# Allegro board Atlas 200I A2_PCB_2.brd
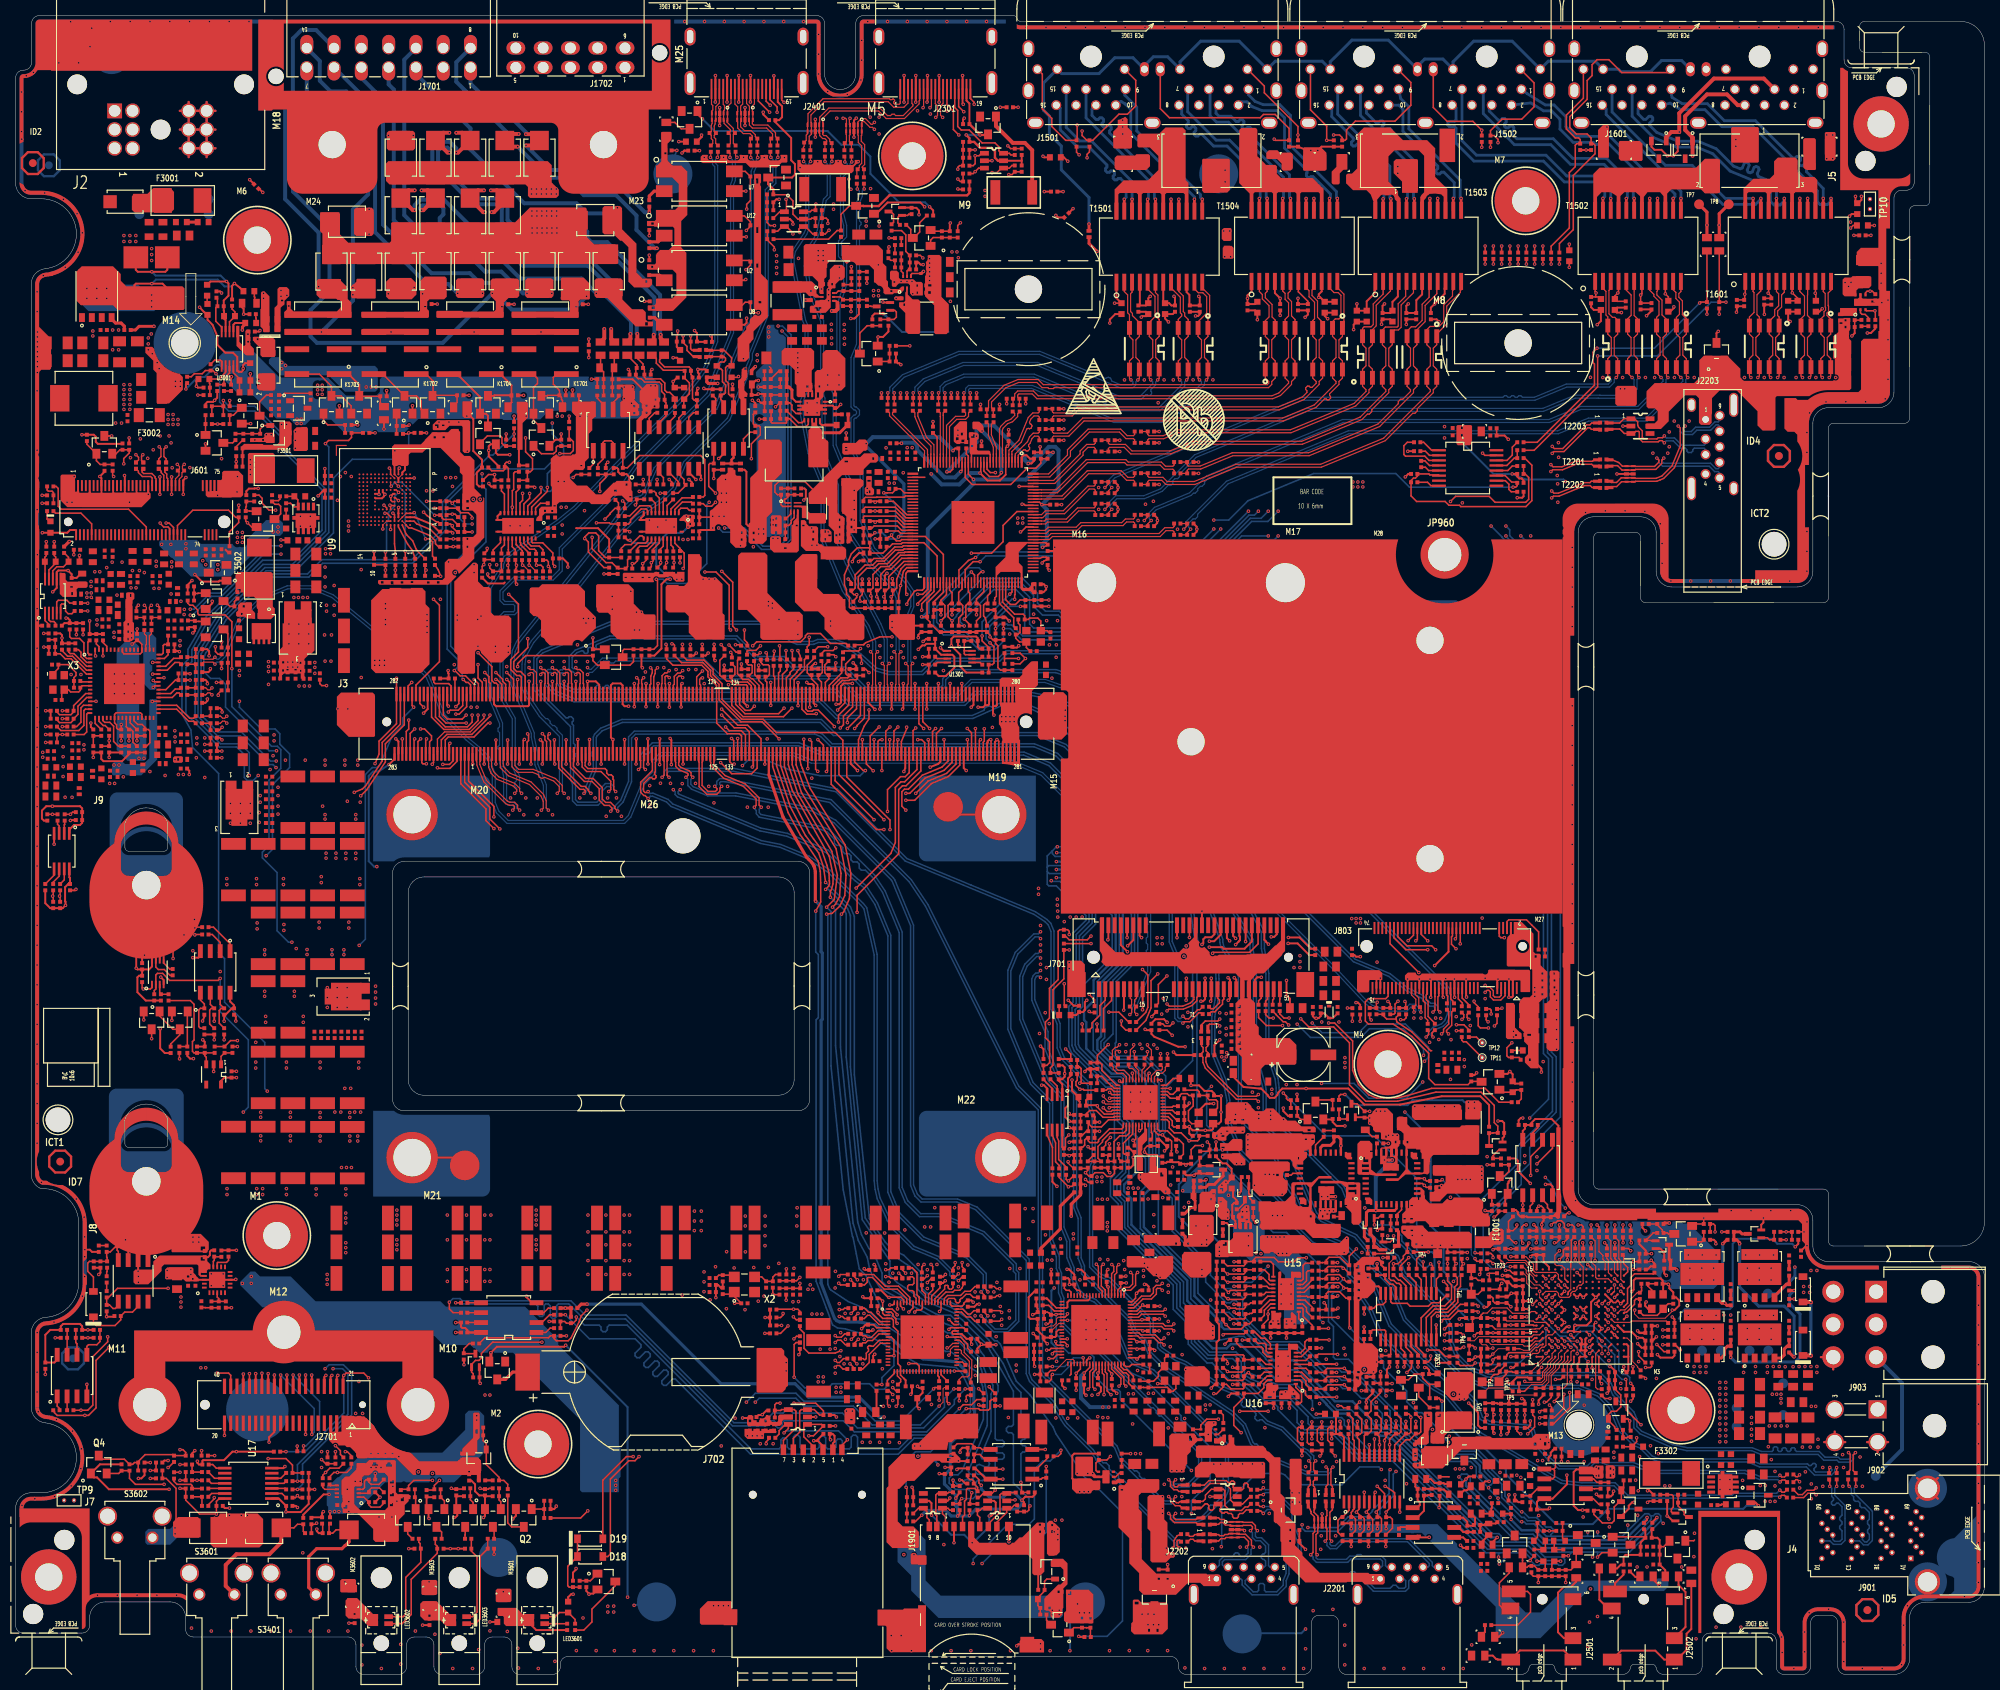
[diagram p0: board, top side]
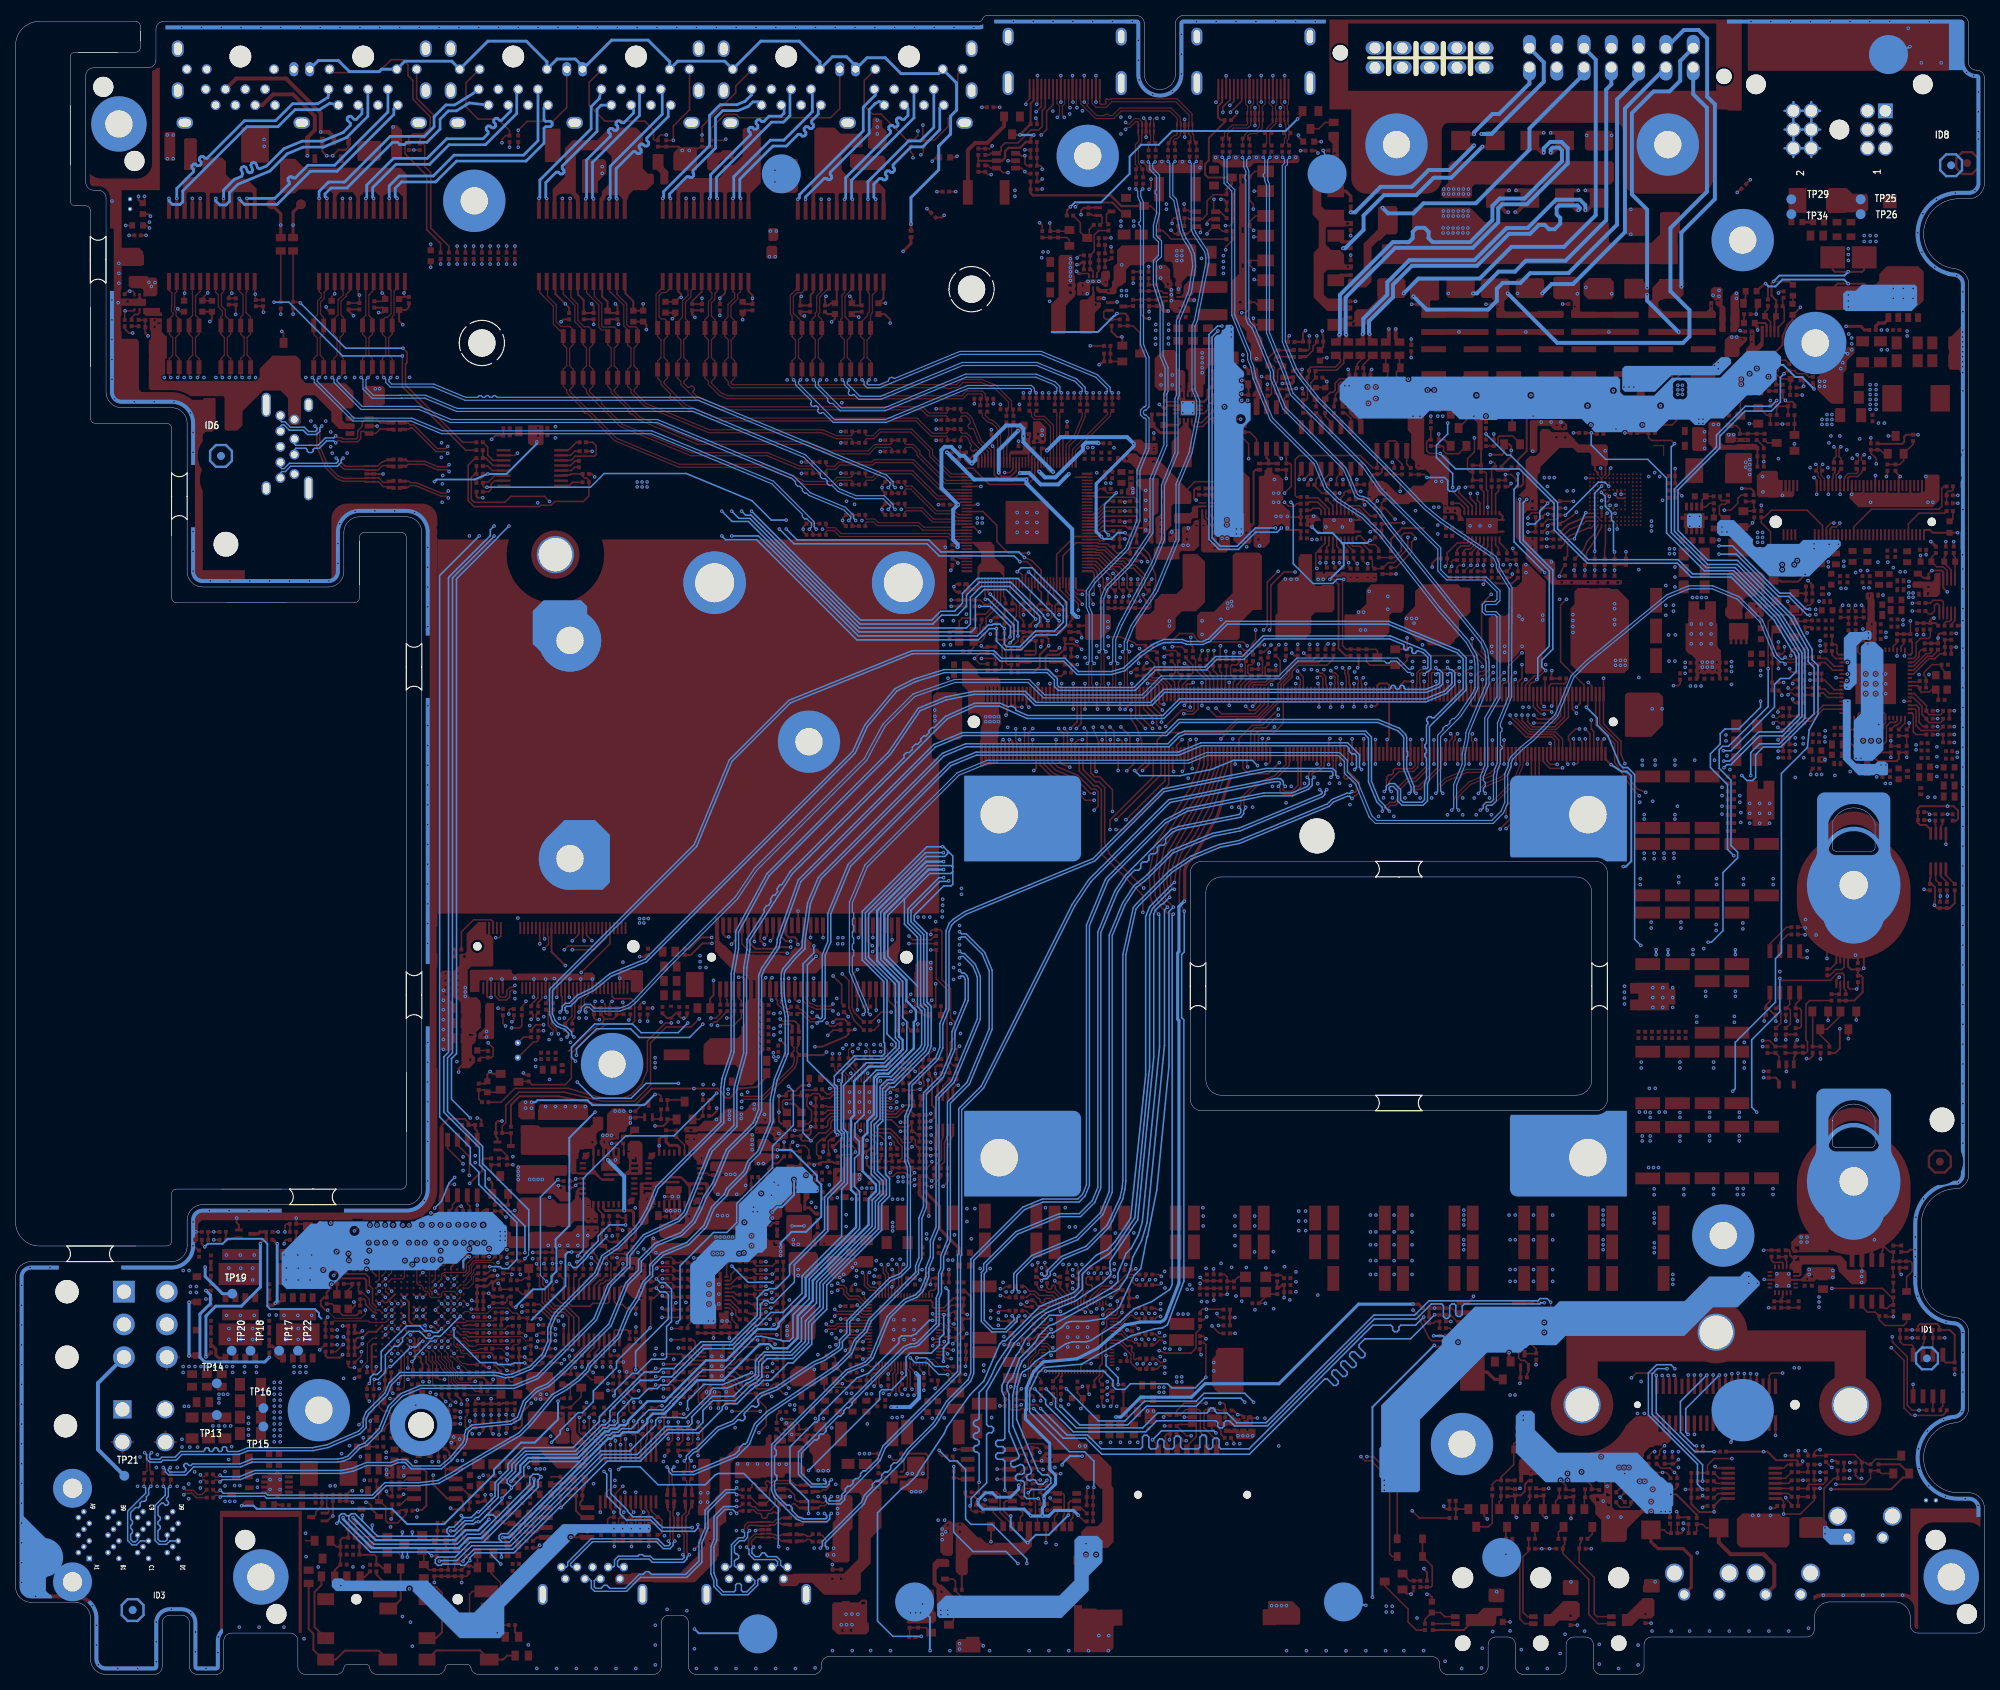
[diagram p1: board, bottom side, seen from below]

Outline 252.5 x 212.8 mm; copper layers: TOP, ART02, ART03, ART04, ART05, BOTTOM. Coordinates in mm from the lower left corner of the outline.

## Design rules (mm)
constraint set DEFAULT: min track width 0.203
net group $7N63630: nets $7N63630 MDI_PHY0_0_N
net group $7N63631: nets $7N63631 MDI_PHY0_1_N
net group $7N63632: nets $7N63632 MDI_PHY0_1_P
net group $7N63633: nets $7N63633 MDI_PHY0_2_N
net group $7N63634: nets $7N63634 MDI_PHY0_2_P
net group $7N63635: nets $7N63635 MDI_PHY0_3_N
net group $7N63636: nets $7N63636 MDI_PHY0_3_P
net group $7N63637: nets $7N63637 MDI_PHY0_0_P
net group $8N44589: nets 8367_XTAL_OUT $8N44589
net group $8N114764: nets $8N114764 MDIO_V33
net group $9N34271: nets $9N34271 $9N34317
net group $9N34280: nets $9N34280 EMMC_DS
net group $9N34284: nets $9N34284 /EMMC_RESET
net group $9N34299: nets $9N34299 EMMC_CLK
net group $9N48264: nets $9N48264 EMMC_CMD
net group $12N159487: nets $12N159487 I2C7_SDA_R
net group $12N159488: nets $12N159488 I2C7_SCL_R
net group $12N159489: nets $12N159489 I2C7_SCL
net group $12N159490: nets $12N159490 I2C7_SDA
net group $20N137120: nets $20N137120 $20N206729
net group $20N155998: nets $20N155998 $20N155999
net group $20N181729: nets $20N181729 $20N206297
net group $20N182987: nets $20N182987 $20N182988
net group $46N78710: nets $46N78710 /PERST_M2_R
net group $46N78948: nets $46N78948 DEVSLP_M2
net group $47N42209: nets $47N42209 SERDES4_TX_N
net group $47N42210: nets $47N42210 SERDES4_TX_P
net group $47N73755: nets $47N73755 SPI0_CS0
net group $47N73822: nets $47N73822 SPI0_MOSI
net group $47N73889: nets $47N73889 SPI0_MISO
net group $47N73956: nets $47N73956 SPI0_CLK
net group $48N218402: nets $48N218402 I2C8_SDA_R
net group $48N218403: nets $48N218403 I2C8_SCL_R
net group $48N218404: nets $48N218404 I2C8_SCL
net group $48N218405: nets $48N218405 I2C8_SDA
net group $49N882: nets $49N882 $49N886
net group $49N883: nets $49N883 $49N885
net group $49N884: nets $49N884 UART2_RX_R
net group $49N3011: nets $49N3011 $49N3019
net group $49N3012: nets $49N3012 $49N3020
net group $49N3013: nets $49N3013 $49N3021
net group $49N3014: nets $49N3014 $49N3022
net group $49N3015: nets $49N3015 UART3_RX_R
net group $49N3026: nets $49N3026 UART0_RX_R
net group $49N114415: nets $49N114415 CAN0_RX_R
net group $51N3749: nets $51N3749 SPI_MCU_MISO
net group $51N3757: nets $51N3757 MCU1_SWDIO
net group $51N24526: nets $51N24526 MCU1_SWCLK
net group $51N107406: nets $51N107406 EN_MCU_HOT2
net group $51N107414: nets $51N107414 EN_MCU_HOT1
net group $51N178691: nets $51N178691 POWER_LED_MCU_R
net group $51N179012: nets $51N179012 HEALTHY_LED_MCU_R
net group $51N179013: nets $51N179013 POWER_LED_MCU_G
net group $51N179014: nets $51N179014 HEALTHY_LED_MCU_G
net group $51N190892: nets $51N190892 I2CS_SCL
net group $51N190893: nets $51N190893 I2CS_SDA
net group $51N190894: nets $51N190894 I2C0_MCU_SDA
net group $51N190895: nets $51N190895 I2C6_SCL
net group $51N190896: nets $51N190896 I2C6_SDA
net group $51N190897: nets $51N190897 I2C0_MCU_SCL
net group $51N230666: nets $51N230666 /FACTORYSET_MCU
net group $51N230667: nets $51N230667 /POWER_BTN_MCU
net group $51N230670: nets $51N230670 /RST_BTN_MCU
net group $51N231131: nets $51N231131 SYS_RST_OUT_R
net group $51N231578: nets 1911_HBOOT_OK_R $51N231578
net group $51N231581: nets $51N231581 HOT_RST_FAULT_R
net group $51N231582: nets 1911_OS_OK_R $51N231582
net group $51N234739: nets $51N234739 /RST_MCU_1911_R
net group $51N235080: nets $51N235080 RSV_GPIO_R
net group $51N235403: nets $51N235403 UHT_ALARM
net group $51N235404: nets $51N235404 FACTORYSET_1911_R
net group $51N243463: nets $51N243463 INT_1911_MCU_R
net group $51N243466: nets $51N243466 INT_MCU_1911_R
net group $51N249168: nets $51N249168 TPM_TYPE
net group $51N266287: nets $51N266287 SPI_MCU_CLK
net group $51N266288: nets $51N266288 SPI_MCU_MOSI
net group $51N266290: nets $51N266290 SPI_MCU_CS
net group $51N266293: nets $51N266293 UART1_RX_R
net group $51N277380: nets $51N277380 MCU2_SWDIO
net group $51N277381: nets $51N277381 MCU2_SWCLK
net group $52N3046: nets $52N3046 /CLKREQ_5G_LTE
net group $52N3047: nets $52N3047 /PEWAKE_5G_LTE
net group $52N52006: nets $52N52006 /PERST_5G_LTE
net group $52N58402: nets $52N58402 SERDES3_TX_N
net group $52N58403: nets $52N58403 SERDES3_TX_P
net group $52N66878: nets $52N66878 PWR_EN_5G
net group $52N90661: nets $52N90661 USB30_5G_HUB_RX_P
net group $52N90662: nets $52N90662 USB30_5G_HUB_RX_N
net group $52N90958: nets $52N90958 USB30_5G_HUB_TX_P
net group $52N90959: nets $52N90959 USB30_5G_HUB_TX_N
net group $53N3925: nets $53N3925 SERDES2_TX_N
net group $53N3926: nets $53N3926 SERDES2_TX_P
net group $53N3927: nets $53N3927 SERDES1_TX_N
net group $53N3928: nets $53N3928 SERDES1_TX_P
net group $53N4325: nets $53N4325 SERDES2_RX_N
net group $53N4326: nets $53N4326 SERDES2_RX_P
net group $53N4327: nets $53N4327 SERDES1_RX_N
net group $53N4328: nets $53N4328 SERDES1_RX_P
net group $61N1210: nets $61N1210 TEC_TRIM2
net group $61N12078: nets $61N12078 EN_TEC_FORWARD
net group $61N12079: nets $61N12079 /EN_TEC_BACKWARD
net group $61N12080: nets $61N12080 EN_TEC_PWR
net group $61N12081: nets $61N12081 /TEC_TRIM2_ON
net group $61N12082: nets $61N12082 /TEC_TRIM1_ON
net group $61N12083: nets $61N12083 MCU_EN_VCC_DISK
net group $61N12094: nets $61N12094 POWER_EN
net group $61N14206: nets 3V3_PWR_EN $61N14206
net group $61N14207: nets $61N14207 HUB_PWR_EN
net group $61N14208: nets 4G_PWR_EN $61N14208
net group $61N14209: nets 5G_PWR_EN $61N14209
net group $61N15063: nets $61N15063 PG_ADJ_TEC
net group $66N179179: nets $66N179179 TAISHAN_SLEEP_IN
net group $66N179181: nets $66N179181 TAISHAN_SLEEP_OUT
net group $66N179183: nets $66N179183 CAN0_RX
net group $66N179184: nets $66N179184 UART3_RX
net group $66N179185: nets $66N179185 UART2_RX
net group $66N179186: nets $66N179186 UART0_RX
net group $66N179206: nets $66N179206 CAN0_TX
net group $66N179207: nets $66N179207 UART3_TX
net group $66N179210: nets $66N179210 UART2_TX
net group $66N179211: nets $66N179211 UART0_TX
net group $66N179213: nets $66N179213 CAN0_TX_R
net group $66N179214: nets $66N179214 UART3_TX_R
net group $66N179215: nets $66N179215 UART2_TX_R
net group $66N179216: nets $66N179216 UART0_TX_R
net group $66N179233: nets $66N179233 TAISHAN_POWEROFF_IN
net group $66N179234: nets $66N179234 TAISHAN_POWEROFF_OUT
net group $66N179235: nets $66N179235 UART1_RX
net group $66N179236: nets $66N179236 UART1_TX
net group $66N179237: nets $66N179237 UART_RTX_EN
net group $66N179252: nets $66N179252 UART1_TX_R
net group $66N371722: nets $66N371722 BOOT_SEL2_R
net group $66N371723: nets $66N371723 BOOT_SEL2
net group $66N371725: nets $66N371725 INT_1911_MCU
net group $66N371730: nets $66N371730 /WAKE_PHY0
net group $66N371774: nets $66N371774 HOT_RST_FAULT
net group $71N10810: nets $71N10810 $71N10812
net group $73N2320: nets $73N2320 /RST_ADM6823
net group /LED_M2_R: nets /LED_M2_R M2_LED
net group CLK_100M_5G_L2_N: nets CLK_100M_5G_L2_N CLK_100M_BUF_5G_L1_N
net group CLK_100M_5G_L2_P: nets CLK_100M_5G_L2_P CLK_100M_BUF_5G_L1_P
net group CLK_100M_BUF_M2_L1_N: nets CLK_100M_BUF_M2_L1_N CLK_100M_M2_L2_N
net group CLK_100M_BUF_M2_L1_P: nets CLK_100M_BUF_M2_L1_P CLK_100M_M2_L2_P
net group CLK_100M_BUF_PCIE_L1_N: nets CLK_100M_BUF_PCIE_L1_N CLK_100M_PCIE_L2_N
net group CLK_100M_BUF_PCIE_L1_P: nets CLK_100M_BUF_PCIE_L1_P CLK_100M_PCIE_L2_P
net group CLK_100M_BUF_WIFI_L1_N: nets CLK_100M_BUF_WIFI_L1_N CLK_100M_WIFI_L2_N
net group CLK_100M_BUF_WIFI_L1_P: nets CLK_100M_BUF_WIFI_L1_P CLK_100M_WIFI_L2_P
net group EMMC_DATA0: nets EMMC_DATA0 EMMC_DATA0_R
net group EMMC_DATA1: nets EMMC_DATA1 EMMC_DATA1_R
net group EMMC_DATA2: nets EMMC_DATA2 EMMC_DATA2_R
net group EMMC_DATA3: nets EMMC_DATA3 EMMC_DATA3_R
net group EMMC_DATA4: nets EMMC_DATA4 EMMC_DATA4_R
net group EMMC_DATA5: nets EMMC_DATA5 EMMC_DATA5_R
net group EMMC_DATA6: nets EMMC_DATA6 EMMC_DATA6_R
net group EMMC_DATA7: nets EMMC_DATA7 EMMC_DATA7_R
net group HDMI0_TX0_C_N: nets HDMI0_TX0_C_N HDMI0_TX0_N
net group HDMI0_TX0_C_P: nets HDMI0_TX0_C_P HDMI0_TX0_P
net group HDMI0_TX1_C_N: nets HDMI0_TX1_C_N HDMI0_TX1_N
net group HDMI0_TX1_C_P: nets HDMI0_TX1_C_P HDMI0_TX1_P
net group HDMI0_TX2_C_N: nets HDMI0_TX2_C_N HDMI0_TX2_N
net group HDMI0_TX2_C_P: nets HDMI0_TX2_C_P HDMI0_TX2_P
net group HDMI0_TXC_C_N: nets HDMI0_TXC_C_N HDMI0_TXC_N
net group HDMI0_TXC_C_P: nets HDMI0_TXC_C_P HDMI0_TXC_P
net group HDMI1_TX0_C_N: nets HDMI1_TX0_C_N HDMI1_TX0_N
net group HDMI1_TX0_C_P: nets HDMI1_TX0_C_P HDMI1_TX0_P
net group HDMI1_TX1_C_N: nets HDMI1_TX1_C_N HDMI1_TX1_N
net group HDMI1_TX1_C_P: nets HDMI1_TX1_C_P HDMI1_TX1_P
net group HDMI1_TX2_C_N: nets HDMI1_TX2_C_N HDMI1_TX2_N
net group HDMI1_TX2_C_P: nets HDMI1_TX2_C_P HDMI1_TX2_P
net group HDMI1_TXC_C_N: nets HDMI1_TXC_C_N HDMI1_TXC_N
net group HDMI1_TXC_C_P: nets HDMI1_TXC_C_P HDMI1_TXC_P
net group MUSIM1_CLK: nets MUSIM1_CLK USIM0_CLK
net group MUSIM1_DATA: nets MUSIM1_DATA USIM0_DATA
net group MUSIM1_RST: nets MUSIM1_RST USIM0_RST
net group RGMII0_RXCK: nets RGMII0_RXCK RGMII_CLK_PHY0
net group RGMII0_RXD0: nets RGMII0_RXD0 RGMII_PHY0_D0
net group RGMII0_RXD1: nets RGMII0_RXD1 RGMII_PHY0_D1
net group RGMII0_RXD2: nets RGMII0_RXD2 RGMII_PHY0_D2
net group RGMII0_RXD3: nets RGMII0_RXD3 RGMII_PHY0_D3
net group RGMII0_RXDV: nets RGMII0_RXDV RGMII_DV_PHY0
net group RGMII1_RXCK: nets RGMII1_RXCK RGMII1_RXCK_R
net group RGMII1_RXD1: nets RGMII1_RXD1 RGMII1_RXD1_R
net group RGMII1_RXD2: nets RGMII1_RXD2 RGMII1_RXD2_R
net group RGMII1_RXD3: nets RGMII1_RXD3 RGMII1_RXD3_R
net group RGMII1_RXDV: nets RGMII1_RXDV RGMII1_RXDV_R
net group SDIO_CLK: nets SD_CLK SDIO_CLK
net group SDIO_CMD: nets SD_CMD SDIO_CMD
net group SDIO_DATA0: nets SD_DATA0 SDIO_DATA0
net group SDIO_DATA1: nets SD_DATA1 SDIO_DATA1
net group SDIO_DATA2: nets SD_DATA2 SDIO_DATA2
net group SDIO_DATA3: nets SD_DATA3 SDIO_DATA3
net group WANGKOUQIAN: nets RS232_RX RS232_TX
net group 12V: nets $20N181730 $63N1364 $67N1257 $67N25230 $73N2325 SENSE_VIN_12V0 V_12V0_CON_IN V_12V0_IN V_12V0_SENSE V_STBY_TEC_12V0 VDD
net group $9N34275: nets $9N34275
net group $12N62032: nets $12N62032 SPI_MISO_HUB SPI_MISO_HUB0 SPI_MISO_HUB1
net group $12N62037: nets $12N62037 SPI_CLK_HUB0 SPI_SCK_HUB SPI_SCK_HUB1
net group $12N65908: nets $12N65908 SPI_CS_HUB SPI_CS_HUB0 SPI_CS_HUB1
net group $12N67333: nets $12N67333 SPI_MOSI_HUB SPI_MOSI_HUB0 SPI_MOSI_HUB1
net group $20N51827: nets $20N51827 $20N51829 $20N51834
net group $48N193018: nets $48N193018 $48N361364 TPM_CS_N
net group $48N195194: nets $48N195194 $48N361357 TPM_CLK
net group $48N306521: nets $48N306521 $48N361367 TPM_MISO
net group $48N306854: nets $48N306854 $48N361356 TPM_MOSI
net group $48N361353: nets $48N361353 SPI2_CLK SPI2_CLK_R
net group $48N361355: nets $48N361355 SPI2_MOSI SPI2_MOSI_R
net group $48N361360: nets $48N361360 SPI2_CS0 SPI2_CS0_R
net group $48N361361: nets $48N361361 SPI2_MISO SPI2_MISO_R
net group $49N888: nets $49N888 $66N179254 UART_RTX_EN_R
net group $51N190904: nets $51N190904 $51N218765 $51N218772 $51N218780 I2C3_MCU_SDA
net group $51N190905: nets $51N190905 $51N218764 $51N218773 $51N218779 I2C3_MCU_SCL
net group $51N221791: nets $51N221791 $61N12065 I2C4_MCU_SDA
net group $51N221836: nets $51N221836 $61N12066 I2C4_MCU_SCL
net group $51N231127: nets $51N231127 $66N179251 TAISHAN_SLEEP_OUT_R
net group $51N231129: nets $51N231129 $66N179253 TAISHAN_POROFF_OUT
net group $51N234742: nets $51N234742 $66N179178 TAISHAN_SLEEP_IN_R
net group $51N234743: nets $51N234743 $66N179250 TAISHAN_POROFF_IN
net group $62N1670: nets $62N1670 $62N1673 PWR_TEC_FORWARD
net group $62N1672: nets $62N1672 $62N1688 PWR_TEC_BACKWARD
net group DVDDIO_1: nets DVDDIO_1 RGMII1_RXD0 RGMII1_RXD0_R
net group POWER: nets V_BAT_3V0 V_LTV_3V3 V_SDCARD_V33 V_VCC_LED_3V3 V_VDDI_EMMC
net group RST: nets /RST_Q_ADM6823 /RST_SPIRST_TPM /RST_USB_HUB_R /RTL8367_RST RGMII0_RST RGMII0_RST_R RGMII1_RST SYS_RST_OUT
net group V_AVDD_1V0_PHY0: nets V_DVDD_1V0_PHY0

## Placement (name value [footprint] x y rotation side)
C1  470pF*  [SC0402-PA]  168.66 58.73 180 top
C2  10uF  [SC1206-TD]  169.11 55.8 270 top
C3  10uF  [SC1206-TD]  166.95 55.8 270 top
C4  22uF  [SC0805-TD]  161.01 69.37 90 top
C5  22uF  [SC0805-TD]  159.26 69.37 90 top
C6  1uF  [SC0603-TB]  164.31 69.37 90 top
C7  22uF  [SC0805-TD]  162.77 69.37 90 top
C8  10nF  [SC0402-PB]  166.88 58.74 0 top
C9  10uF  [SC1206-TD]  162.32 61.39 90 top
C10  1uF  [SC0603-TB]  208.03 29.21 0 top
C11  15pF  [SC0402-PB]  212.6 47.95 270 top
C12  15pF  [SC0402-PB]  210.82 50.11 0 top
C13  100nF  [SC0402-PB]  192.91 47.88 180 top
C14  100nF  [SC0402-PB]  192.91 48.89 180 top
C15  100nF  [SC0402-PB]  191.34 50.72 90 top
C16  100nF  [SC0402-PB]  192.38 50.22 90 top
C17  100nF  [SC0402-PB]  193.29 50.22 90 top
C18  100nF  [SC0402-PB]  209.42 40.97 0 top
C19  100nF  [SC0402-PB]  207.01 38.76 0 top
C20  100nF  [SC0402-PB]  195.05 54.23 90 top
C21  100nF  [SC0402-PB]  209.42 42.82 0 top
C22  100nF  [SC0402-PB]  209.42 41.91 0 top
C23  100nF  [SC0402-PB]  192.91 46.86 180 top
C24  100nF  [SC0402-PB]  195.96 54.23 90 top
C25  100nF  [SC0402-PB]  208.66 53.97 0 top
C26  100nF  [SC0402-PB]  208.66 52.96 0 top
C27  100nF  [SC0402-PB]  191.21 48.06 90 top
C28  100nF  [SC0402-PB]  190.07 48.06 90 top
C29  100nF  [SC0402-PB]  209.42 44.73 0 top
C30  100nF  [SC0402-PB]  209.42 43.81 0 top
C31  100nF  [SC0402-PB]  192.76 45.85 180 top
C32  10uF  [SC0603B]  201.04 35.94 180 top
C33  100nF  [SC0402-PB]  201.3 37.21 180 top
C34  100nF  [SC0402-PB]  195.07 56.51 90 top
C35  100nF  [SC0402-PB]  199.9 56.51 90 top
C36  100nF*  [SC0402-PB]  194.16 56.51 90 top
C37  10uF  [SC1206-TD]  160.22 61.39 90 top
C38  100nF  [SC0603-TC]  27.43 174.24 0 top
C39  10uF  [SC0603B]  37.72 159.51 0 top
C40  100nF  [SC0402-PB]  40.07 153.75 0 top
C41  10nF  [SC0402-PB]  40.07 152.81 0 top
C42  100nF  [SC0402-PB]  109.88 51.89 180 top
C43  10uF  [SC1206-TD]  15.62 169.67 270 top
C44  10uF  [SC1206-TD]  13.34 169.67 270 top
C45  1nF  [SC0402-PA]  14.35 161.16 270 top
C46  10uF  [SC1206-TD]  182.58 70.43 90 top
C47  10uF  [SC1206-TD]  186.81 66.01 270 top
C48  22uF  [SC0805-TD]  183.8 57.07 270 top
C49  22uF  [SC0805-TD]  182.09 60.35 90 top
C50  1uF  [SC0603-TB]  180.15 57.89 270 top
C51  22uF  [SC0805-TD]  181.94 57.07 270 top
C52  10nF  [SC0402-PB]  177.75 68.27 180 top
C53  470pF*  [SC0402-PA]  175.01 68.98 0 top
C54  10uF  [SC1206-TD]  176.45 70.64 180 top
C55  10uF  [SC1206-TD]  184.68 70.46 90 top
C56  22uF  [SC1206-TF]  157 27.25 270 top
C57  22uF  [SC1206-TF]  154.76 27.25 270 top
C58  22uF  [SC1206-TF]  159.2 27.23 270 top
C59  22uF  [SC1206-TF]  162.84 26.83 0 top
C60  22uF  [SC1206-TF]  162.84 24.62 0 top
C61  22uF  [SC1206-TF]  144.65 19.9 0 top
C62  22uF  [SC1206-TF]  144.65 22.11 0 top
C63  22uF  [SC1206-TF]  143.53 25.65 90 top
C64  22uF  [SC1206-TF]  145.07 15.48 0 top
C65  22uF  [SC1206-TF]  145.73 25.67 90 top
C66  22uF  [SC1206-TF]  236.12 170.23 0 top
C67  22uF  [SC1206-TF]  236.12 168.02 0 top
C68  22uF  [SC1206-TF]  236.12 165.79 0 top
C69  22uF  [SC1206-TF]  208.51 163.63 180 top
C70  22uF  [SC1206-TF]  226.34 162.89 0 top
C71  10uF  [SC1206-TD]  145.07 17.64 0 top
C72  10uF  [SC1206-TD]  226.34 160.55 0 top
C73  10uF  [SC1206-TD]  152.2 27.25 270 top
C74  10uF  [SC1206-TD]  17.45 163.83 180 top
C75  10uF  [SC1206-TD]  17.45 166.12 180 top
C76  10nF*  [SC0402-PB]  89.41 49.96 180 top
C77  15pF*  [SC0402-PB]  89.41 49.05 180 top
C78  100nF*  [SC0402-PB]  99.71 49.12 90 top
C79  100pF  [SC0402-PA]  57.48 40.8 270 top
C80  100nF  [SC0402-PB]  59.09 38.1 180 top
C81  100nF  [SC0603-TC]  24.61 175.11 270 top
C82  100nF  [SC0402-PB]  178.11 57.71 270 top
C83  10nF  [SC0402-PB]  235.03 25.42 90 top
C84  22uF  [SC0805-TD]  168.53 88.96 180 top
C85  22uF  [SC0805-TD]  164.25 85.47 180 top
C86  22uF  [SC0805-TD]  195.74 85.48 0 top
C87  22uF  [SC0805-TD]  168.53 90.81 180 top
C88  12pF  [SC0402-PA]  169.55 85.22 270 top
C89  27pF  [SC0402-PA]  167.39 85.22 270 top
C90  100nF  [SC0402-PB]  171.4 92.68 270 top
C91  22uF  [SC0805-TD]  168.71 92.71 180 top
C92  1uF  [SC0402-PD]  166.37 85.22 270 top
C93  1nF  [SC0402-PA]  186.69 76.48 270 top
C94  10nF  [SC0402-PB]  235.99 25.42 90 top
C95  10nF  [SC0402-PB]  232.59 25.42 90 top
C96  10nF  [SC0402-PB]  233.55 25.42 90 top
C97  15pF  [SC0402-PB]  112.5 139.47 270 top
C98  100nF*  [SC0402-PB]  124.64 49.76 0 top
C99  100nF*  [SC0402-PB]  124.64 48.37 0 top
C100  100nF*  [SC0402-PB]  120.22 51.39 90 top
C101  100nF*  [SC0402-PB]  121.62 51.39 90 top
C102  220nF  [SC0402]  162.99 44.2 90 top
C103  33pF  [SC0402]  104 31.88 180 top
C104  33pF  [SC0402]  104.01 33.27 180 top
C105  33pF  [SC0402]  96.97 33.86 180 top
C106  220nF  [SC0402]  164.01 44.2 90 top
C107  220nF  [SC0402]  161.98 44.2 90 top
C108  220nF  [SC0402]  160.96 44.2 90 top
C109  220nF  [SC0402]  154.83 55.85 270 top
C110  220nF  [SC0402]  179.48 27.25 270 top
C111  27pF  [SC0402-PA]  97.27 31.69 270 top
C112  330uF  [SCAPC2-0707B]  165.17 79.48 0 top
C113  1nF  [SC0402-PA]  38.32 82.04 270 top
C114  1nF  [SC0402-PA]  39.19 82.04 270 top
C115  1nF  [SC0402-PA]  40.05 82.04 270 top
C116  1nF  [SC0402-PA]  40.92 82.04 270 top
C117  1nF  [SC0402-PA]  41.78 82.04 270 top
C118  1nF  [SC0402-PA]  42.64 82.04 270 top
C119  1nF  [SC0402-PA]  43.51 82.04 270 top
C120  1nF  [SC0402-PA]  44.37 82.04 270 top
C121  22pF  [SC0402-PA]  96.26 50.02 270 top
C122  22pF  [SC0402-PA]  93.47 47.61 0 top
C123  100nF  [SC0402-PB]  149.88 17.99 0 top
C124  100nF  [SC0402-PB]  149.88 17.03 0 top
C125  100nF  [SC0603-TC]  131.45 128.22 0 top
C126  100nF  [SC0603-TC]  131.45 129.54 0 top
C127  100nF  [SC0402-PB]  166.77 25.52 270 top
C128  100nF  [SC0402-PB]  165.81 25.52 270 top
C129  220nF  [SC0402]  162.36 35.2 90 top
C130  220nF  [SC0402]  163.37 35.2 90 top
C131  1uF*  [SC0402-PD]  168.5 46.79 0 top
C132  10nF*  [SC0402-PB]  19.3 155.07 270 top
C133  10nF*  [SC0402-PB]  18.36 155.07 270 top
C134  10nF*  [SC0402-PB]  16.38 155.07 270 top
C135  10nF*  [SC0402-PB]  15.44 155.07 270 top
C136  10nF  [SC0402-PB]  59.56 31.67 180 top
C137  1uF  [SC0402-PD]  68.2 21.21 0 top
C138  100nF  [SC0402-PB]  130.66 137.42 270 top
C139  100nF  [SC0603-TC]  199.26 181.99 90 top
C140  8.2pF  [SC0402-PA]  5.08 129.54 0 top
C141  8.2pF  [SC0402-PA]  5.51 125.01 0 top
C142  1uF  [SC0603-TB]  21.61 118.51 180 top
C143  100nF  [SC0402-PB]  21.61 120.59 180 top
C144  100nF  [SC0402-PB]  21.61 119.62 180 top
C145  1uF  [SC0603-TB]  11 115.53 270 top
C146  100nF  [SC0402-PB]  13.08 115.53 270 top
C147  100nF  [SC0402-PB]  12.11 115.53 270 top
C148  1uF  [SC0603-TB]  19.64 140.5 90 top
C149  100nF  [SC0402-PB]  17.56 140.5 90 top
C150  100nF  [SC0402-PB]  18.53 140.5 90 top
C151  1uF  [SC0603-TB]  20.18 136.51 0 top
C152  100nF  [SC0402-PB]  19.96 135.2 0 top
C153  100nF  [SC0402-PB]  19.96 134.17 0 top
C154  10uF*  [SC0603B]  4.52 112.62 180 top
C155  10uF*  [SC0603B]  4.52 114.03 180 top
C156  1uF  [SC0603-TB]  15.04 116.33 270 top
C157  100nF  [SC0402-PB]  15.59 133.07 90 top
C158  100nF  [SC0402-PB]  13.55 120.81 270 top
C159  10uF  [SC1206-TD]  236.86 180.09 90 top
C160  10uF  [SC1206-TD]  136.99 25.83 90 top
C161  10uF  [SC1206-TD]  149.34 30.43 90 top
C162  100nF*  [SC0402-PB]  59.82 24.89 180 top
C163  100nF  [SC0402-PB]  93.98 164.13 180 top
C164  220nF  [SC0402]  160.33 35.2 90 top
C165  220nF  [SC0402]  161.34 35.2 90 top
C166  100nF  [SC0402-PB]  35.1 21.61 0 top
C167  100nF  [SC0402-PB]  26.16 21.61 180 top
C168  100nF*  [SC0402-PB]  16.13 26.16 0 top
C170  100nF*  [SC0402-PB]  80.26 131.1 270 top
C171  5pF  [SC0402-PA]  102.08 128.6 90 top
C172  5pF  [SC0402-PA]  102.95 128.6 90 top
C173  5pF  [SC0402-PA]  104.29 128.6 90 top
C174  5pF  [SC0402-PA]  105.54 128.9 180 top
C175  5pF  [SC0402-PA]  106.96 128.57 90 top
C176  5pF  [SC0402-PA]  107.82 128.55 90 top
C177  5pF  [SC0402-PA]  90.88 128.4 90 top
C178  5pF  [SC0402-PA]  91.75 128.4 90 top
C179  5pF  [SC0402-PA]  93.09 128.55 90 top
C180  5pF  [SC0402-PA]  93.95 128.55 90 top
C181  5pF  [SC0402-PA]  95.3 128.4 90 top
C182  5pF  [SC0402-PA]  96.16 128.4 90 top
C183  5pF  [SC0402-PA]  140.28 67.03 90 top
C184  5pF  [SC0402-PA]  142.62 67.16 90 top
C185  5pF  [SC0402-PA]  137.8 71.71 0 top
C186  5pF  [SC0402-PA]  137.97 70.85 0 top
C187  5pF  [SC0402-PA]  136.17 66.64 180 top
C188  5pF  [SC0402-PA]  138.37 65.4 270 top
C189  5pF  [SC0402-PA]  111.48 139.47 270 top
C190  5pF  [SC0402-PA]  110.46 139.47 270 top
C191  5pF  [SC0402-PA]  109.45 139.47 270 top
C192  5pF  [SC0402-PA]  108.59 139.47 270 top
C193  5pF  [SC0402-PA]  107.16 139.47 270 top
C301  100pF  [SC0402-PA]  4.66 130.93 0 top
C401  100nF  [SC0402-PB]  7.67 117.56 180 top
C402  10uF  [SC0603B]  13.8 135.9 180 top
C403  100nF  [SC0402-PB]  7.67 118.53 180 top
C404  1uF  [SC0603-TB]  7.67 116.45 180 top
C405  100nF  [SC0402-PB]  13.7 134.72 180 top
C406  100nF  [SC0402-PB]  13.7 133.75 180 top
C407  100pF  [SC0402-PA]  7.67 119.47 180 top
C408  1uF  [SC0603-TB]  4.52 116.36 0 top
C409  100nF  [SC0402-PB]  4.52 118.44 0 top
C410  220pF  [SC0402-PA]  13.7 132.81 180 top
C411  1uF  [SC0603-TB]  13.8 137.23 180 top
C412  100nF  [SC0402-PB]  18.81 120.51 0 top
C413  10uF  [SC0603B]  7.67 115.12 180 top
C414  100nF  [SC0402-PB]  4.52 117.47 0 top
C415  1uF  [SC0603-TB]  18.86 117.97 0 top
C416  10uF  [SC0603B]  18.86 119.3 0 top
C417  100pF  [SC0402-PA]  18.81 121.45 0 top
C418  100pF  [SC0402-PA]  15.64 140.5 90 top
C419  100nF  [SC0402-PB]  14.7 140.5 90 top
C420  1uF  [SC0603-TB]  12.19 140.47 90 top
C421  10uF  [SC0603B]  13.52 140.47 90 top
C422  100pF  [SC0402-PA]  11.53 134.41 180 top
C423  100nF  [SC0402-PB]  11.53 135.35 180 top
C424  1uF  [SC0603-TB]  11.33 137.86 180 top
C425  10uF  [SC0603B]  11.33 136.53 180 top
C426  100nF  [SC0402-PB]  21.59 116.2 0 top
C601  100nF*  [SC0402-PB]  11.4 154.81 270 top
C603  100nF  [SC0402-PB]  11.43 143.76 270 top
C604  100nF  [SC0402-PB]  25.4 143.94 270 top
C605  10uF  [SC0603B]  16.91 143.42 270 top
C606  10uF  [SC0603B]  20.96 143.1 270 top
C607  100nF  [SC0402-PB]  12.45 143.76 270 top
C608  100nF  [SC0402-PB]  26.42 143.94 270 top
C609  10uF  [SC0603B]  19.05 143.1 270 top
C610  10uF  [SC0603B]  15.01 143.42 270 top
C619  100nF  [SC0402-PB]  7.87 144.27 180 top
C620  100nF  [SC0402-PB]  24.38 143.94 270 top
C621  10uF  [SC0603B]  22.86 143.1 270 top
C622  10uF  [SC0603B]  9.91 143.38 270 top
C701  33pF  [SC0402]  190.5 69.47 0 top
C706  10uF  [SC0603B]  159.96 76.06 0 top
C707  10nF  [SC0402-PB]  156.34 81.2 180 top
C708  10pF  [SC0402]  156.34 83.03 180 top
C709  1uF  [SC0402-PD]  156.34 84.9 180 top
C710  10nF*  [SC0402-PB]  146.28 85.39 270 top
C711  100nF  [SC0402-PB]  154.69 80.26 90 top
C712  1uF  [SC0402-PD]  156.34 80.24 180 top
C713  1nF  [SC0402-PA]  189.48 65.79 270 top
C714  1nF  [SC0402-PA]  189.33 59.84 270 top
C715  10pF*  [SC0402]  153.34 79.43 0 top
C716  10pF*  [SC0402]  151.59 79.45 180 top
C717  100nF  [SC0402-PB]  156.34 82.12 180 top
C718  100nF  [SC0402-PB]  156.34 83.94 180 top
C719  100nF  [SC0402-PB]  156.34 85.87 180 top
C722  220nF  [SC0402]  152.65 85.65 0 top
C723  220nF  [SC0402]  152.65 84.71 0 top
C724  1uF*  [SC0402-PD]  94.62 33.02 0 top
C725  1uF  [SC0402-PD]  104.01 30.86 180 top
C726  10nF  [SC0402-PB]  94.17 31.69 270 top
C727  10nF  [SC0402-PB]  95.19 31.69 270 top
C728  1uF  [SC0402-PD]  96.2 31.69 270 top
C731  100nF  [SC0402-PB]  136.4 85.37 90 top
C802  1uF  [SC0603-TB]  192 75.39 90 top
C810  100nF  [SC0402-PB]  182.02 83.06 90 top
C811  100nF  [SC0402-PB]  181.1 83.06 90 top
C814  22uF  [SC0805-TD]  192.5 83.54 180 top
C815  22uF  [SC0805-TD]  192.5 85.48 180 top
C816  22uF  [SC0805-TD]  168.53 87.12 180 top
C817  22uF  [SC0805-TD]  195.74 83.54 0 top
C818  12pF  [SC0402-PA]  196.6 88.14 0 top
C819  27pF  [SC0402-PA]  196.6 89.92 0 top
C820  100nF  [SC0402-PB]  196.6 89.03 0 top
C821  22uF  [SC0805-TD]  195.74 81.61 0 top
C822  1uF  [SC0402-PD]  196.6 87.2 0 top
C834  10uF  [SC0603B]  184.2 77.57 180 top
C835  100nF  [SC0402-PB]  184.2 79.35 90 top
C836  100nF  [SC0402-PB]  185.12 79.35 90 top
C837  1uF  [SC0402-PD]  183.24 79.35 90 top
C839  100nF  [SC0402-PB]  193.22 82.04 180 top
C901  10nF  [SC0402-PB]  227.58 23.7 0 top
C902  10uF  [SC1206-TD]  229.87 31.62 270 top
C903  10uF  [SC1206-TD]  225.65 31.62 270 top
C904  10uF  [SC1206-TD]  227.76 31.62 270 top
C905  2.2uF  [SC0805-TD]  228.47 34.92 0 top
C906  2.2uF  [SC0805-TD]  223.39 27.69 0 top
C907  2.2uF  [SC0805-TD]  227.97 37.72 90 top
C908  10uF  [SC1206-TD]  222.38 33 180 top
C909  2.2uF  [SC0805-TD]  226.06 37.72 90 top
C910  2.2uF  [SC0805-TD]  223.39 25.65 0 top
C911  2.2uF  [SC0805-TD]  229.87 37.72 90 top
C913  10nF  [SC0402-PB]  227.57 22.68 0 top
C915  10nF  [SC0402-PB]  227.6 25.65 0 top
C916  10nF  [SC0402-PB]  227.6 24.66 0 top
C1001  1nF  [SC0402-PA]  163.96 71.65 180 top
C1002  10nF  [SC0402-PB]  169.32 71.25 180 top
C1003  10uF  [SC1206-TD]  182.6 65.99 270 top
C1004  10uF  [SC1206-TD]  180.47 70.43 90 top
C1005  10uF  [SC1206-TD]  184.71 66.01 270 top
C1008  22uF  [SC1206-TF]  185.88 56.83 270 top
C1009  22uF  [SC1206-TF]  186.53 61.12 90 top
C1010  22uF  [SC1206-TF]  184.32 61.12 90 top
C1011  1nF*  [SC0402-PA]  173.01 71.83 270 top
C1012  100nF  [SC0402-PB]  203.78 25.5 0 top
C1013  10uF  [SC0603B]  206.63 23.62 0 top
C1014  100nF  [SC0402-PB]  206.63 24.89 0 top
C1015  100nF*  [SC0402-PB]  203.78 22.83 0 top
C1016  100nF  [SC0402-PB]  173.49 51.67 90 top
C1101  100nF*  [SC0402-PB]  227.46 44.96 90 top
C1102  100nF*  [SC0402-PB]  219.96 44.96 90 top
C1103  100nF*  [SC0402-PB]  227.46 53.34 270 top
C1104  100nF*  [SC0402-PB]  219.96 49.66 270 top
C1105  100nF  [SC0402-PB]  225.93 55.75 0 top
C1106  10nF  [SC0402-PB]  208.65 55.68 180 top
C1107  100pF*  [SC0402-PA]  211.84 53.09 180 top
C1108  100nF  [SC0402-PB]  216.92 55.75 0 top
C1201  10pF  [SC0402]  138.3 76.73 0 top
C1202  27pF  [SC0402-PA]  149.48 73.91 0 top
C1203  27pF  [SC0402-PA]  153.29 74.27 180 top
C1204  10uF  [SC0603B]  141.28 62.43 90 top
C1205  100nF  [SC0402-PB]  143.56 61.34 90 top
C1206  100nF  [SC0402-PB]  142.65 61.34 90 top
C1207  1uF  [SC0402-PD]  144.53 61.34 90 top
C1208  100nF  [SC0402-PB]  149.48 64.39 180 top
C1209  100nF  [SC0402-PB]  149.48 63.45 180 top
C1210  1uF  [SC0402-PD]  147.83 61.47 90 top
C1211  10uF  [SC0603B]  146.18 61.92 90 top
C1212  1uF  [SC0402-PD]  148.97 61.47 90 top
C1213  10nF  [SC0402-PB]  138.74 78.08 270 top
C1214  4.7uF  [SC0603-TD]  137.01 74.07 0 top
C1215  100nF  [SC0402-PB]  136.88 72.97 0 top
C1216  10uF  [SC0603B]  156.54 67.17 90 top
C1217  100nF  [SC0402-PB]  156.39 70.41 270 top
C1218  100nF  [SC0402-PB]  155.37 70.41 270 top
C1219  1uF  [SC0402-PD]  157.4 70.41 270 top
C1220  10nF  [SC0402-PB]  143.51 67.44 90 top
C1301  3.9pF  [SC0402-PA]  145.61 152.65 0 top
C1302  3.9pF  [SC0402-PA]  150.66 155.52 0 top
C1303  3.9pF  [SC0402-PA]  150.66 154.07 0 top
C1304  3.9pF  [SC0402-PA]  140.55 158.33 0 top
C1305  3.9pF  [SC0402-PA]  140.55 156.88 0 top
C1306  3.9pF  [SC0402-PA]  145.61 159.44 0 top
C1307  3.9pF  [SC0402-PA]  145.61 157.99 0 top
C1308  3.9pF  [SC0402-PA]  145.61 154.1 0 top
C1309  3.9pF  [SC0402-PA]  140.55 151.53 0 top
C1310  3.9pF  [SC0402-PA]  150.66 146.19 0 top
C1311  3.9pF  [SC0402-PA]  145.61 148.76 0 top
C1312  3.9pF  [SC0402-PA]  145.61 147.31 0 top
C1313  3.9pF  [SC0402-PA]  140.55 150.18 0 top
C1314  3.9pF  [SC0402-PA]  140.55 148.73 0 top
C1315  3.9pF  [SC0402-PA]  140.55 152.98 0 top
C1316  3.9pF  [SC0402-PA]  150.66 147.64 0 top
C1317  15pF  [SC0402-PB]  113.24 137.2 90 top
C1318  27pF  [SC0402-PA]  132.72 133.3 270 top
C1319  27pF  [SC0402-PA]  130.56 131.27 0 top
C1320  100nF  [SC0402-PB]  117.53 132.84 0 top
C1321  100nF  [SC0402-PB]  121.26 132.59 0 top
C1322  3.9pF  [SC0402-PA]  133.38 159.77 0 top
C1323  3.9pF  [SC0402-PA]  125.79 162.28 0 top
C1324  3.9pF  [SC0402-PA]  124.16 162.28 180 top
C1325  3.9pF  [SC0402-PA]  129.14 163.65 0 top
C1326  3.9pF  [SC0402-PA]  127.51 163.65 180 top
C1327  3.9pF  [SC0402-PA]  133.38 160.91 0 top
C1328  3.9pF  [SC0402-PA]  133.38 162.36 0 top
C1329  3.9pF  [SC0402-PA]  133.38 158.32 0 top
C1330  3.9pF  [SC0402-PA]  121.21 163.75 180 top
C1331  3.9pF  [SC0402-PA]  113.09 163.75 0 top
C1332  3.9pF  [SC0402-PA]  111.46 163.75 180 top
C1333  3.9pF  [SC0402-PA]  116.34 163.75 0 top
C1334  3.9pF  [SC0402-PA]  114.71 163.75 180 top
C1335  3.9pF  [SC0402-PA]  119.59 163.75 0 top
C1336  3.9pF  [SC0402-PA]  117.96 163.75 180 top
C1337  3.9pF  [SC0402-PA]  122.84 163.75 0 top
C1401  1nF  [SC0402-PA]  117.31 135.67 0 top
C1402  1nF  [SC0402-PA]  112.45 152.09 180 top
C1403  1nF  [SC0402-PA]  109.14 145.19 180 top
C1404  100nF  [SC0402-PB]  106.53 158.11 90 top
C1405  100nF  [SC0402-PB]  123.47 157.56 0 top
C1406  100nF  [SC0402-PB]  131.06 138.84 0 top
C1407  100nF  [SC0402-PB]  130.61 156.36 90 top
C1408  1nF  [SC0402-PA]  103.07 146.58 180 top
C1409  100nF  [SC0402-PB]  115.39 156.34 90 top
C1410  100nF  [SC0402-PB]  113.25 156.34 90 top
C1411  1nF  [SC0402-PA]  117.81 136.97 270 top
C1412  100nF  [SC0402-PB]  109.14 146.13 180 top
C1413  100nF  [SC0402-PB]  114.32 156.34 90 top
C1414  100nF  [SC0402-PB]  127.36 158.62 90 top
C1415  100nF  [SC0402-PB]  132.36 144.53 270 top
C1416  100nF  [SC0402-PB]  131.06 139.85 0 top
C1417  100nF  [SC0402-PB]  112.78 153.87 270 top
C1418  100nF  [SC0402-PB]  111.86 153.87 270 top
C1419  100nF  [SC0402-PB]  133.1 150.06 0 top
C1420  100nF  [SC0402-PB]  125.54 136.97 270 top
C1421  100nF  [SC0402-PB]  122.15 159.08 180 top
C1422  100nF  [SC0402-PB]  132.36 142.72 270 top
C1423  100nF  [SC0402-PB]  112.19 156.34 90 top
C1424  2.2uF  [SC0402-PD]  117.65 159.66 90 top
C1425  2.2uF  [SC0402-PD]  120.9 157.69 90 top
C1426  10nF  [SC0402-PB]  106.43 148.13 180 top
C1427  1uF  [SC0402-PD]  111.3 144.65 180 top
C1428  1uF  [SC0402-PD]  111.3 145.67 180 top
C1429  1uF  [SC0402-PD]  121.92 157.69 90 top
C1430  1uF  [SC0402-PD]  116.18 134.13 90 top
C1431  1uF  [SC0402-PD]  103.07 145.59 180 top
C1432  1uF  [SC0402-PD]  106.43 147.17 0 top
C1433  10uF  [SC0603B]  110.68 153.56 270 top
C1434  1nF  [SC0402-PA]  98.32 148.28 0 top
C1435  10uF  [SC0603B]  100.61 146.54 0 top
C1436  100nF  [SC0402-PB]  100.61 147.73 0 top
C1437  100nF  [SC0402-PB]  106.43 145.35 0 top
C1438  27pF  [SC0402-PA]  99.03 151.74 270 top
C1439  10uF  [SC0603B]  100.61 145.13 0 top
C1440  1nF  [SC0402-PA]  98.32 147.4 180 top
C1441  22uF  [SC0805-TD]  105.69 151.33 0 top
C1442  22uF  [SC0805-TD]  105.69 149.52 0 top
C1443  10uF  [SC0603B]  108.2 153.56 270 top
C1445  22uF  [SC0805-TD]  106.53 153.78 270 top
C1501  100nF  [SC0402-PB]  151.87 175.21 90 top
C1502  100nF  [SC0402-PB]  148.69 175.21 90 top
C1503  100nF  [SC0402-PB]  143.99 175.21 90 top
C1504  100nF  [SC0402-PB]  150.6 175.21 90 top
C1505  1uF  [SC0603-TB]  141.83 175.21 90 top
C1506  1uF  [SC0603-TB]  147.42 175.21 90 top
C1507  1uF  [SC0603-TB]  145.26 175.21 90 top
C1508  1nF  [SC1206E]  142.04 195.07 90 top
C1509  100nF  [SC0402-PB]  208.41 175.51 90 top
C1510  100nF  [SC0402-PB]  209.8 175.51 90 top
C1511  100nF  [SC0402-PB]  206.5 175.74 90 top
C1512  100nF  [SC0402-PB]  202.06 176.3 90 top
C1513  1uF  [SC0603-TB]  211.96 175.51 90 top
C1514  1uF  [SC0603-TB]  205.11 175.74 90 top
C1515  1uF  [SC0603-TB]  203.31 175.74 90 top
C1516  100nF  [SC0402-PB]  175.31 174.24 90 top
C1517  100nF  [SC0402-PB]  179.63 174.24 90 top
C1518  100nF  [SC0402-PB]  178.36 174.24 90 top
C1519  100nF  [SC0402-PB]  181.51 174.24 90 top
C1520  1uF  [SC0603-TB]  176.58 174.24 90 top
C1521  1uF  [SC0603-TB]  172.01 174.24 90 top
C1522  1uF  [SC0603-TB]  173.28 174.24 90 top
C1523  100nF  [SC0402-PB]  157.99 175.39 90 top
C1524  100nF  [SC0402-PB]  165.74 175.39 90 top
C1525  100nF  [SC0402-PB]  164.47 175.39 90 top
C1526  100nF  [SC0402-PB]  162.18 175.39 90 top
C1527  1uF  [SC0603-TB]  159.26 175.39 90 top
C1528  1uF  [SC0603-TB]  167.89 175.39 90 top
C1529  1uF  [SC0603-TB]  169.16 175.39 90 top
C1530  10nF  [SC0402-PB]  136.07 196.39 270 top
C1531  10nF  [SC0402-PB]  137.72 196.39 270 top
C1532  10nF  [SC0402-PB]  164.47 196.39 270 top
C1533  10nF  [SC0402-PB]  163.32 196.39 270 top
C1534  10nF  [SC0402-PB]  189.15 197 270 top
C1535  10nF  [SC0402-PB]  188.04 197 270 top
C1536  10nF  [SC0402-PB]  170.13 196.39 270 top
C1537  10nF  [SC0402-PB]  169.06 196.39 270 top
C1538  1nF  [SC1206E]  164.43 194 0 top
C1539  1nF  [SC1206E]  168.81 194 180 top
C1540  1nF  [SC1206E]  204.98 195.58 180 top
C1601  100pF  [SC0402-PA]  76.94 165.12 180 top
C1602  100pF  [SC0402-PA]  75.01 165.15 180 top
C1603  100nF  [SC0402-PB]  71.83 164.08 180 top
C1604  100nF  [SC0402-PB]  189.54 158.93 180 top
C1605  100nF  [SC0402-PB]  179.76 158.06 0 top
C1606  1nF  [SC0402-PA]  216.92 175.64 90 top
C1607  1nF  [SC0402-PA]  218.49 175.64 90 top
C1608  1nF  [SC0402-PA]  87.22 166.36 0 top
C1609  1nF  [SC0402-PA]  85.32 166.36 180 top
C1610  1nF  [SC0402-PA]  81.05 166.74 0 top
C1611  1nF  [SC0402-PA]  79.14 166.74 180 top
C1612  100nF  [SC0402-PB]  179.76 156.92 180 top
C1613  100nF  [SC0402-PB]  179.38 154 180 top
C1614  100nF  [SC0402-PB]  180.26 155.27 90 top
C1615  1nF  [SC0402-PA]  80.14 161.8 180 top
C1616  10uF  [SC0603B]  79.76 164.13 180 top
C1617  100nF  [SC0402-PB]  80.14 162.69 180 top
C1620  100nF  [SC0402-PB]  225.17 176.12 90 top
C1621  100nF  [SC0402-PB]  220.75 175.92 90 top
C1622  100nF  [SC0402-PB]  221.69 175.92 90 top
C1623  100nF  [SC0402-PB]  224.26 176.12 90 top
C1624  1uF  [SC0603-TB]  228.55 175.51 90 top
C1625  1uF  [SC0603-TB]  227.33 175.51 90 top
C1626  1uF  [SC0603-TB]  230.89 175.51 90 top
C1627  1nF  [SC1206E]  231.34 195.99 0 top
C1628  10nF  [SC0402-PB]  202.06 195.96 270 top
C1629  10nF  [SC0402-PB]  200.66 195.96 270 top
C1630  100nF  [SC0603-TC]  155.35 183.59 90 top
C1631  100nF  [SC0603-TC]  86.67 196.63 0 top
C1632  100nF  [SC0603-TC]  32.89 173.85 180 top
C1633  100nF  [SC0603-TC]  32.89 172.6 180 top
C1634  100nF  [SC0603-TC]  85.22 169.21 270 top
C1635  100nF  [SC0603-TC]  133.35 194.61 0 top
C1636  100nF  [SC0603-TC]  236.19 188.04 270 top
C1637  100nF  [SC0603-TC]  236.86 185.88 180 top
C1638  100nF  [SC0402-PB]  91.82 154.93 270 top
C1639  10uF  [SC0603B]  93.73 165.48 0 top
C1640  100pF  [SC0402-PA]  90.42 164.46 90 top
C1641  100pF  [SC0402-PA]  91.95 164.46 90 top
C1642  100pF  [SC0402-PA]  86.98 170.98 0 top
C1643  100pF  [SC0402-PA]  85.21 170.98 180 top
C1644  10nF  [SC0402-PB]  88.65 166.8 270 top
C1645  100nF  [SC0402-PB]  184.71 159.89 0 top
C1646  100nF  [SC0402-PB]  184.71 158.95 0 top
C1647  100nF  [SC0402-PB]  189.54 159.87 180 top
C1701  10nF*  [SC0402-PB]  69.98 157.99 90 top
C1702  100nF  [SC0402-PB]  70.16 164.08 0 top
C1703  100nF  [SC0402-PB]  83.72 195.5 180 top
C1704  100nF  [SC0402-PB]  81.27 185.71 90 top
C1705  100nF  [SC0402-PB]  81.27 181.01 270 top
C1706  100nF  [SC0402-PB]  81.34 175.74 270 top
C1707  10nF*  [SC0402-PB]  49.28 160.16 0 top
C1708  100nF  [SC0402-PB]  57.02 164.08 0 top
C1709  10nF*  [SC0402-PB]  42.67 160.28 0 top
C1710  100nF  [SC0402-PB]  47.18 163.96 0 top
C1711  10nF*  [SC0402-PB]  62.92 157.99 90 top
C1712  100nF  [SC0402-PB]  64.01 164.08 0 top
C1801  10nF  [SC0402-PB]  30.35 158.75 270 top
C1802  10nF  [SC0402-PB]  33.78 161.92 270 top
C1803  1uF  [SC0402-PD]  27.05 160.4 180 top
C1805  10nF  [SC0402-PB]  28.7 154.94 0 top
C1806  100nF  [SC0402-PB]  28.7 156.29 0 top
C1809  10uF  [SC0603B]  57.15 157.86 180 top
C1811  22pF*  [SC0402-PA]  57.15 147.45 180 top
C1812  10nF  [SC0402-PB]  45.97 142.75 270 top
C1813  100nF  [SC0402-PB]  54.86 146.6 0 top
C1814  100nF*  [SC0402-PB]  28.7 157.28 0 top
C1815  1uF  [SC0402-PD]  24.77 160.4 0 top
C1816  100nF*  [SC0402-PB]  37.84 163.93 270 top
C1818  10uF  [SC0603B]  37.72 157.61 180 top
C1819  100nF  [SC0402-PB]  40.08 150.95 180 top
C1820  100nF  [SC0402-PB]  40.07 151.88 180 top
C1821  10uF  [SC0603B]  57.15 159.26 0 top
C1822  100nF  [SC0402-PB]  54.86 159.49 90 top
C1823  100nF  [SC0402-PB]  53.8 159.49 90 top
C1901  100nF*  [SC0402-PB]  114.72 21.69 0 top
C1902  10uF*  [SC0603B]  132.17 15.75 0 top
C1903  10uF  [SC0603B]  132.17 17.11 0 top
C1904  100nF  [SC0402-PB]  131.56 10.85 0 top
C1905  4.7uF  [SC0603-TD]  131.81 9.66 180 top
C1906  100nF*  [SC0402-PB]  132.17 18.29 0 top
C1907  100nF  [SC0402-PB]  134.55 10.59 0 top
C1908  100nF  [SC0402-PB]  136.76 6.4 90 top
C1909  10uF  [SC0603B]  134.61 9.2 0 top
C2001  100nF*  [SC0402-PB]  57.53 43.87 180 top
C2002  100nF*  [SC0402-PB]  141.73 50.62 90 top
C2003  100nF*  [SC0402-PB]  139.93 50.75 270 top
C2004  100nF*  [SC0402-PB]  138.18 50.42 270 top
C2005  100nF*  [SC0402-PB]  137.16 50.42 270 top
C2006  100nF*  [SC0402-PB]  135.79 50.42 270 top
C2007  100nF*  [SC0402-PB]  134.62 37.72 180 top
C2008  100nF*  [SC0402-PB]  136.02 37.59 270 top
C2009  100nF*  [SC0402-PB]  137.03 37.59 270 top
C2010  100nF*  [SC0402-PB]  138.81 37.62 270 top
C2011  100nF*  [SC0402-PB]  140.59 37.49 90 top
C2012  100nF*  [SC0402-PB]  145.03 40.77 0 top
C2013  100nF*  [SC0402-PB]  145.03 41.76 0 top
C2014  100nF*  [SC0402-PB]  145.03 42.67 0 top
C2015  100nF*  [SC0402-PB]  145.62 44.07 0 top
C2016  100nF*  [SC0402-PB]  144.91 49.28 0 top
C2017  100nF*  [SC0402-PB]  145.64 47.24 0 top
C2018  100nF*  [SC0402-PB]  145.64 45.59 0 top
C2019  100nF*  [SC0402-PB]  131.32 48.23 180 top
C2020  100nF*  [SC0402-PB]  131.45 43.2 0 top
C2021  100nF*  [SC0402-PB]  133.22 51.31 0 top
C2022  18pF*  [SC0402-PA]  148.08 40.89 0 top
C2023  18pF*  [SC0402-PA]  147.57 36.32 180 top
C2024  100nF  [SC0402-PB]  134.44 67.06 270 top
C2025  100nF  [SC0402-PB]  133.78 78.54 270 top
C2026  100nF*  [SC0402-PB]  133.22 50.29 180 top
C2027  10uF*  [SC1206-TD]  147.45 54.36 270 top
C2028  10uF*  [SC1206-TD]  143.38 54.36 270 top
C2029  100nF*  [SC0402-PB]  131.03 40.46 180 top
C2030  100nF*  [SC0402-PB]  131.03 42.29 180 top
C2031  100nF*  [SC0402-PB]  131.03 41.38 180 top
C2032  100nF*  [SC0402-PB]  136.17 54.38 90 top
C2033  10uF*  [SC1206-TD]  139.45 55.4 0 top
C2034  100nF*  [SC0402-PB]  134.11 54.48 270 top
C2035  100nF*  [SC0402-PB]  133.1 54.48 270 top
C2036  4.7uF*  [SC0603-TD]  130.81 52.45 0 top
C2037  4.7uF*  [SC0603-TD]  130.81 54.1 0 top
C2038  10uF*  [SC0603B]  146.94 34.42 270 top
C2039  10uF*  [SC0603B]  143.38 34.42 270 top
C2040  10uF*  [SC0603B]  148.72 34.42 270 top
C2041  4.7uF*  [SC0603-TD]  135.53 34.34 270 top
C2042  4.7uF*  [SC0603-TD]  134.21 34.34 270 top
C2043  100nF*  [SC0402-PB]  140.97 34.8 90 top
C2044  100nF*  [SC0402-PB]  141.99 34.8 90 top
C2045  10uF*  [SC0603B]  151.03 33.96 180 top
C2046  10uF*  [SC0603B]  151.03 35.76 180 top
C2047  10uF*  [SC0603B]  145.16 34.42 270 top
C2103  100nF*  [SC0402-PB]  107.19 43.69 0 top
C2104  100nF  [SC0402-PB]  108 43.69 180 top
C2105  100nF  [SC0402-PB]  108 42.29 180 top
C2106  100nF*  [SC0402-PB]  107.19 42.29 0 top
C2107  100nF  [SC0402-PB]  117.63 50.34 90 top
C2108  100nF*  [SC0402-PB]  117.63 51.16 270 top
C2109  100nF  [SC0402-PB]  116.23 50.34 90 top
C2110  100nF*  [SC0402-PB]  116.23 51.16 270 top
C2111  100nF  [SC0402-PB]  110.11 49.28 180 top
C2112  10uF  [SC0603B]  109.09 31.37 270 top
C2113  10uF  [SC0603B]  112.21 31.37 270 top
C2114  100nF  [SC0402-PB]  122.94 41.4 0 top
C2115  100nF  [SC0402-PB]  121.92 44.58 270 top
C2116  100nF  [SC0402-PB]  110.13 47.24 180 top
C2117  10nF  [SC0402-PB]  114.55 36.96 180 top
C2118  10uF  [SC0603B]  110.85 31.37 90 top
C2119  4.7uF  [SC0603-TD]  124.78 42.99 270 top
C2120  100nF  [SC0402-PB]  118.56 50.61 90 top
C2121  10uF  [SC0603B]  107.32 37.08 180 top
C2122  100nF  [SC0402-PB]  110.39 40.18 180 top
C2123  100nF  [SC0402-PB]  109.32 44.45 270 top
C2124  10uF  [SC0603B]  107.32 35.31 180 top
C2125  100nF  [SC0402-PB]  116.32 37.15 270 top
C2126  100nF  [SC0402-PB]  122.12 47.57 270 top
C2127  100nF  [SC0402-PB]  110.13 48.26 180 top
C2128  100nF  [SC0402-PB]  122.94 43.05 0 top
C2129  4.7uF  [SC0603-TD]  116.33 35.43 180 top
C2130  100nF  [SC0402-PB]  121.61 50.58 270 top
C2131  100nF  [SC0402-PB]  120.22 50.58 270 top
C2132  100nF  [SC0402-PB]  123.82 48.37 180 top
C2133  100nF  [SC0402-PB]  123.82 49.76 180 top
C2202  100nF  [SC0402-PB]  164.24 18.52 180 top
C2206  100nF  [SC0402-PB]  146.61 13.06 270 top
C2210  100nF  [SC0402-PB]  235.46 173.74 180 top
C2301  100nF  [SC0402-PB]  121.92 198.88 180 top
C2302  220nF  [SC0402]  121.92 194.56 0 top
C2303  100nF  [SC0402-PB]  121.92 190.5 180 top
C2401  100nF  [SC0402-PB]  97.03 199.39 180 top
C2402  220nF  [SC0402]  96.77 188.85 0 top
C2403  100nF  [SC0402-PB]  105.85 184.82 270 top
C2501  1nF  [SC0402-PA]  198.8 13 270 top
C2502  1nF  [SC0402-PA]  194.4 13.51 270 top
C2503  15pF  [SC0402-PB]  197.91 13 270 top
C2504  15pF  [SC0402-PB]  195.29 13 270 top
C2505  2.2uF  [SC0402-PD]  194.77 15.62 90 top
C2506  100nF  [SC0402-PB]  195.58 19.43 180 top
C2507  100nF  [SC0402-PB]  197.99 19.43 0 top
C2508  2.2uF  [SC0402-PD]  198.5 15.62 90 top
C2509  1uF  [SC0603-TB]  188.72 15.32 0 top
C2510  100nF  [SC0402-PB]  188.34 13.28 0 top
C2511  100nF  [SC0402-PB]  186.5 22.34 90 top
C2512  1uF  [SC0603-TB]  189.89 24.13 90 top
C2513  100nF  [SC0402-PB]  191.47 25.5 180 top
C2514  1uF  [SC0603-TB]  194.23 24.87 90 top
C2515  100nF  [SC0402-PB]  187.52 22.34 90 top
C2516  100pF  [SC0402-PA]  180.21 22.94 180 top
C2517  10uF  [SC0603B]  187.33 24.13 180 top
C2518  10uF  [SC0603B]  180.21 25.07 0 top
C2519  1nF  [SC0402-PA]  182.63 23.32 270 top
C2520  1nF  [SC0402-PA]  187.45 25.4 0 top
C2521  1nF  [SC0402-PA]  191.77 20.95 90 top
C2522  10uF  [SC0603B]  187.33 20.62 0 top
C2523  1nF  [SC0402-PA]  190.45 19.53 0 top
C2524  10uF  [SC0603B]  188.72 16.64 180 top
C2525  100pF  [SC0402-PA]  186.18 18.67 90 top
C2526  27pF  [SC0402-PA]  209.42 17.53 180 top
C2527  27pF  [SC0402-PA]  210.44 15.37 180 top
C2528  27pF  [SC0402-PA]  208.81 16.38 0 top
C2529  1nF  [SC0402-PA]  206.63 14.07 0 top
C2530  1nF  [SC0402-PA]  210.44 16.38 180 top
C2531  1nF  [SC0402-PA]  208.81 15.37 0 top
C2532  1nF  [SC0402-PA]  210.44 14.1 180 top
C2619  100nF  [SC0402-PB]  23.52 129.59 0 top
C2620  100nF  [SC0402-PB]  23.52 130.5 0 top
C2621  100nF  [SC0402-PB]  25.41 122.94 0 top
C2622  100nF  [SC0402-PB]  25.41 122.02 0 top
C2623  100nF*  [SC0402-PB]  23.52 126.57 0 top
C2624  100nF*  [SC0402-PB]  23.52 125.65 0 top
C2633  100nF  [SC0402-PB]  17.42 135.99 90 top
C2634  100nF  [SC0402-PB]  16.51 135.99 90 top
C2701  100nF  [SC0402-PB]  41.66 21.72 0 top
C2702  100nF  [SC0402-PB]  46.51 27.61 270 top
C2703  100nF  [SC0402-PB]  45.59 27.61 270 top
C2704  10uF  [SC0603B]  44.32 27.43 270 top
C2705  100nF  [SC0402-PB]  47.42 27.61 270 top
C2706  100nF  [SC0402-PB]  48.34 27.61 270 top
C2711  1uF  [SC0603-TB]  168.63 33.43 180 top
C2712  100nF  [SC0402-PB]  169.93 31.24 90 top
C2713  100nF  [SC0402-PB]  6.98 100.99 270 top
C2714  100nF  [SC0402-PB]  8.13 109.6 0 top
C2801  100nF  [SC0402-PB]  193.17 70.48 180 top
C2802  1uF  [SC0402-PD]  204.72 36.7 180 top
C2803  100nF  [SC0402-PB]  204.72 37.74 180 top
C2804  100nF  [SC0402-PB]  207.14 30.86 90 top
C2805  10uF  [SC0603B]  206.63 27.81 0 top
C2806  10uF  [SC0603B]  206.63 26.16 0 top
C2807  10uF  [SC0603B]  203.92 28.16 270 top
C2808  10uF  [SC0603B]  202.56 28.16 270 top
C2809  10uF  [SC0603B]  200.09 28.28 180 top
C2810  100nF  [SC0402-PB]  204.72 38.76 180 top
C2811  100nF  [SC0402-PB]  28.02 85.04 270 top
C2812  100nF  [SC0402-PB]  3.81 39.6 270 top
C2813  100nF  [SC0402-PB]  122.54 26.43 180 top
C2909  220nF  [SC0402]  87.27 147.55 180 top
C2910  220nF  [SC0402]  87.27 148.45 180 top
C2911  220nF  [SC0402]  87.27 146.64 180 top
C2912  220nF  [SC0402]  87.27 145.74 180 top
C2913  220nF  [SC0402]  68.28 148.82 90 top
C2914  220nF  [SC0402]  69.19 148.82 90 top
C2915  220nF  [SC0402]  68.66 147.07 180 top
C2916  220nF  [SC0402]  68.66 146.05 180 top
C2921  10nF*  [SC0402-PB]  21.7 135.2 180 top
C3001  100nF*  [SC0603-TC]  29.92 177.44 0 top
C3002  100nF  [SC0603-TC]  29.41 164.46 0 top
C3003  6.8nF*  [SC0603-TB]  30.15 173.37 0 top
C3004  100nF  [SC0603-TC]  24.16 166.18 0 top
C3005  100nF  [SC0603-TC]  30.09 168.91 270 top
C3006  100nF  [SC0603-TC]  24.05 186.31 0 top
C3007  1uF  [SC0805-TD]  21.49 184.58 0 top
C3008  100nF  [SC0603-TC]  21.26 186.31 0 top
C3009  100nF  [SC0603-TC]  29.41 165.99 0 top
C3010  100nF  [SC0603-TC]  24.56 177.57 270 top
C3011  1nF*  [SC0402-PA]  25.86 165.05 270 top
C3012  100nF  [SC0402-PB]  7.19 140.26 90 top
C3013  10uF  [SC0603B]  8.54 140.51 90 top
C3014  100nF  [SC0603-TC]  4.45 142.75 0 top
C3015  100nF  [SC0603-TC]  7.49 142.75 0 top
C3016  10uF  [SC1206-TD]  5.33 170.81 0 top
C3017  10uF  [SC1206-TD]  9.91 168.53 180 top
C3018  1nF  [SC0402-PA]  11.3 172.47 0 top
C3019  10uF  [SC1206-TD]  5.33 168.53 0 top
C3020  10uF  [SC1206-TD]  9.91 170.81 180 top
C3101  1uF*  [SC0603-TB]  151.77 61.4 180 top
C3102  100nF  [SC0402-PB]  151.84 64.87 90 top
C3103  1nF  [SC0402-PA]  96.44 163.12 180 top
C3104  15pF  [SC0402-PB]  98.48 163.12 180 top
C3105  1nF  [SC0402-PA]  102.34 165.2 0 top
C3106  100nF  [SC0603-TC]  102.21 166.6 0 top
C3107  2.2nF  [SC0402-PB]  105.11 162.05 90 top
C3108  100nF  [SC0402-PB]  93.88 146.43 180 top
C3109  47pF  [SC0402-PA]  98.48 165.15 180 top
C3110  1uF  [SC0603-TB]  105.99 160.27 0 top
C3111  10uF  [SC1206-TD]  103.1 168.88 0 top
C3112  10nF  [SC0402-PB]  98.48 162.1 180 top
C3113  100nF  [SC0402-PB]  98.48 161.09 180 top
C3114  4.7nF  [SC0402-PB]  96.44 164.13 180 top
C3115  22uF  [SC1206-TF]  93.65 150.55 180 top
C3116  22uF  [SC1206-TF]  93.65 152.83 180 top
C3117  22uF  [SC1206-TF]  93.65 148.26 180 top
C3119  10uF  [SC1206-TD]  97.64 168.88 180 top
C3120  22pF  [SC0402-PA]  106.17 177.88 90 top
C3121  100nF  [SC0402-PB]  101.98 176.71 90 top
C3122  22uF  [SC0805-TD]  103.4 171.88 270 top
C3123  22uF  [SC0805-TD]  99.59 171.88 270 top
C3124  22uF  [SC0805-TD]  101.5 171.88 270 top
C3126  100nF  [SC0402-PB]  102.44 174.55 90 top
C3127  1nF  [SC0402-PA]  103.96 178.36 0 top
C3128  100nF  [SC0603-TC]  104.22 179.76 0 top
C3129  10uF  [SC1206-TD]  100.46 182.45 180 top
C3130  100nF  [SC0402-PB]  106.12 175.95 270 top
C3131  10uF  [SC1206-TD]  100.48 180.21 180 top
C3132  10nF  [SC0402-PB]  112.5 168.43 0 top
C3133  10nF  [SC0402-PB]  111.94 173.42 270 top
C3134  22pF  [SC0402-PA]  113.18 180.49 180 top
C3135  100nF  [SC0402-PB]  113.61 176.12 270 top
C3136  22uF  [SC0805-TD]  119 179.25 0 top
C3137  22uF  [SC0805-TD]  119 181.2 0 top
C3138  22uF  [SC0805-TD]  119 177.29 0 top
C3140  100nF  [SC0402-PB]  116.38 177.25 180 top
C3141  1nF  [SC0402-PA]  112.7 177.88 90 top
C3142  100nF  [SC0603-TC]  111.89 179.35 0 top
C3143  10uF  [SC1206-TD]  110.34 183.36 90 top
C3144  100nF  [SC0402-PB]  115.09 180.24 0 top
C3145  10uF  [SC1206-TD]  108.13 183.36 90 top
C3146  10nF  [SC0402-PB]  118.8 184.73 90 top
C3147  10nF  [SC0402-PB]  114.91 187.73 90 top
C3201  10uF  [SC1206-TD]  160.63 56.41 270 top
C3202  10uF  [SC1206-TD]  162.73 56.41 270 top
C3203  10uF  [SC1206-TD]  164.84 56.41 270 top
C3208  22uF  [SC0805-TD]  161.01 65.96 270 top
C3209  22uF  [SC0805-TD]  162.77 65.96 270 top
C3210  22uF  [SC0805-TD]  159.26 65.96 270 top
C3212  100nF  [SC0402-PB]  166.34 69.39 90 top
C3213  100nF  [SC0402-PB]  157.66 63.8 0 top
C3214  1uF*  [SC0603-TB]  155.96 63.04 270 top
C3215  10nF  [SC0402-PB]  27.31 54 90 top
C3216  10uF  [SC0603B]  20.63 53.92 90 top
C3217  10nF  [SC0402-PB]  23.06 50.27 90 top
C3218  22uF  [SC0805-TD]  20.7 50.24 90 top
C3220  100nF  [SC0402-PB]  24.26 53.92 90 top
C3222  10nF  [SC0402-PB]  25.12 47.45 270 top
C3223  10uF  [SC0603B]  22.48 53.92 90 top
C3224  100nF  [SC0402-PB]  26.39 53.97 90 top
C3225  100nF*  [SC0402-PB]  203.78 26.42 0 top
C3301  1uF  [SC0603-TB]  215.77 22.48 90 top
C3302  100nF  [SC0603-TC]  218.72 27.56 90 top
C3303  220nF  [SC0603-TC]  220.04 21.82 0 top
C3304  100nF  [SC0603-TC]  182.37 37.92 90 top
C3305  10uF  [SC1206-TD]  222.38 37.21 180 top
C3306  10uF  [SC1206-TD]  222.38 35.11 180 top
C3307  10uF  [SC1206-TD]  193.17 28.32 270 top
C3308  100nF  [SC0402-PB]  194.9 28.7 270 top
C3309  100nF  [SC0402-PB]  196.15 28.7 270 top
C3310  10uF  [SC1206-TD]  191.05 28.31 270 top
C3311  10uF  [SC1206-TD]  188.95 28.31 270 top
C3312  100nF  [SC0402-PB]  211.81 22.64 270 top
C3313  10uF  [SC1206-TD]  222.38 30.9 180 top
C3314  220nF  [SC0402]  149.64 56.95 270 top
C3315  1uF  [SC0603-TB]  181.74 32.18 0 top
C3316  100nF  [SC0603-TC]  219.99 27.56 90 top
C3401  10nF*  [SC0402-PB]  22.02 80.14 270 top
C3402  100nF  [SC0402-PB]  15.33 54.93 0 top
C3403  1nF  [SC0402-PA]  13.42 54.93 180 top
C3404  100nF  [SC0402-PB]  16.22 90.85 90 top
C3406  100nF  [SC0402-PB]  27.69 76.96 90 top
C3407  100nF*  [SC0402-PB]  24.26 80.14 90 top
C3408  100nF  [SC0402-PB]  39.31 19.75 270 top
C3501  100nF  [SC0603-TC]  35.56 145.48 180 top
C3502  220nF  [SC0603-TC]  34.7 147.7 270 top
C3503  1nF  [SC0402-PA]  37.3 129.77 0 top
C3504  1nF  [SC0402-PA]  35.9 128.14 270 top
C3505  10uF  [SC1206-TD]  37.22 139.51 0 top
C3506  1uF  [SC0603-TB]  36.45 151.13 0 top
C3507  10uF*  [SC1206-TD]  37.22 143.72 0 top
C3508  10uF*  [SC1206-TD]  37.22 141.62 0 top
C3509  1nF  [SC0402-PA]  33.53 128.78 180 top
C3510  100nF  [SC0402-PB]  29.52 148.84 270 top
C3511  1nF  [SC0402-PA]  37.3 128.75 0 top
C3512  1nF  [SC0402-PA]  33.53 129.79 180 top
C3513  1nF  [SC0402-PA]  33.53 127.76 180 top
C3514  1nF  [SC0402-PA]  37.34 127.73 0 top
C3515  1nF  [SC0402-PA]  34.89 128.14 270 top
C3516  100nF*  [SC0603-TC]  38.13 145.48 0 top
C3517  100nF  [SC0603-TC]  29.24 129.67 180 top
C3518  220nF  [SC0603-TC]  28.65 133.5 270 top
C3519  10uF  [SC1206-TD]  30.48 117.35 0 top
C3520  1uF  [SC0603-TB]  30.63 137.11 0 top
C3521  10uF*  [SC1206-TD]  30.48 119.51 0 top
C3522  10uF*  [SC1206-TD]  30.48 121.67 0 top
C3523  100nF  [SC0402-PB]  22.48 138.66 180 top
C3524  100nF*  [SC0603-TC]  29.24 130.92 180 top
C3525  1nF  [SC0402-PA]  32.51 108.2 0 top
C3526  1nF  [SC0402-PA]  32.51 110.24 0 top
C3527  1nF  [SC0402-PA]  32.51 115.16 0 top
C3528  1nF  [SC0402-PA]  32.51 114.3 0 top
C3529  1nF  [SC0402-PA]  32.51 113.28 0 top
